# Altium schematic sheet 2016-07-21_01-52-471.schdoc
size 331 x 127 mm; SheetNumber: 1; SheetTotal: 1
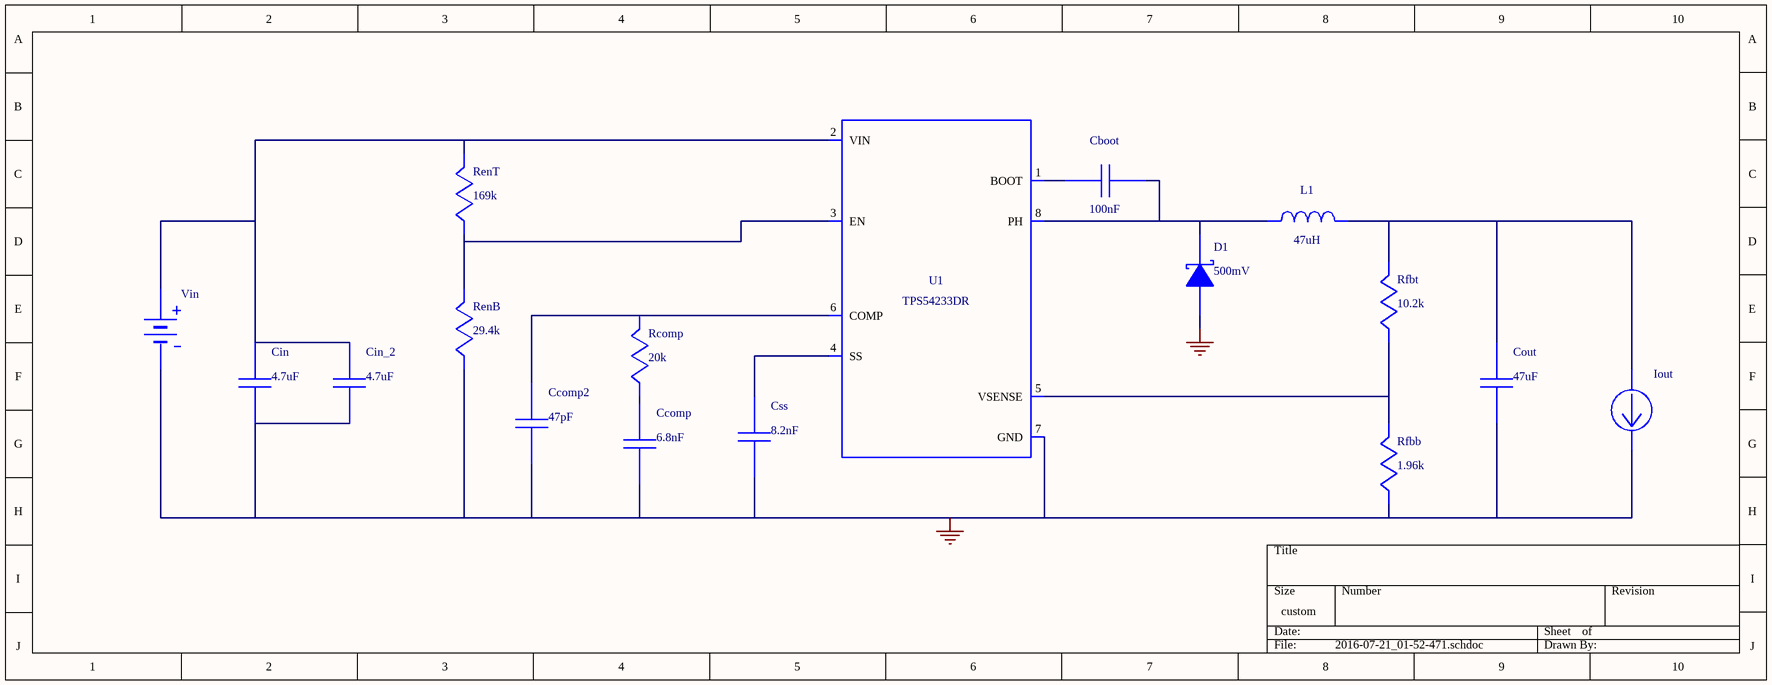
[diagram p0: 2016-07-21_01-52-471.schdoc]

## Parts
Cboot  value 100nF  (hidden comment: GRM155R61A104KA01D)
Ccomp  value 6.8nF  (hidden comment: GRM033R61A682KA01D)
Ccomp2  value 47pF  (hidden comment: CL02C470JO2ANNC)
Cin  value 4.7uF  (hidden comment: GRM32ER71H475KA88L)
Cin_2  value 4.7uF  (hidden comment: GRM32ER71H475KA88L)
Cout  value 47uF  (hidden comment: GRM31CR61A476KE15L)
Css  value 8.2nF  (hidden comment: GRM033R61A822KA01D)
D1  value 500mV  (hidden comment: B240A-13-F)
Iout  WB_CURRENT_LOAD  (value not drawn)
L1  value 47uH  (hidden comment: SRU1048-470Y)
Rcomp  value 20k  (hidden comment: CRCW040220K0FKED)
RenB  value 29.4k  (hidden comment: CRCW040229K4FKED)
RenT  value 169k  (hidden comment: CRCW0402169KFKED)
Rfbb  value 1.96k  (hidden comment: CRCW04021K96FKED)
Rfbt  value 10.2k  (hidden comment: CRCW040210K2FKED)
U1  TPS54231DR  (value not drawn)
Vin  WB_BATTERY  (value not drawn)

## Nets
0: Ccomp.2 Ccomp2.2 Cin.2 Cin_2.2 Cout.2 Css.2 D1.2(A) Iout.2(-) RenB.2 Rfbb.2 U1.7(GND) Vin.2(-)
NetCboot_1: Cboot.1 U1.1(BOOT)
NetCboot_2: Cboot.2 D1.1(K) L1.2 U1.8(PH)
NetCcomp2_1: Ccomp2.1 Rcomp.1 U1.6(COMP)
NetCcomp_1: Ccomp.1 Rcomp.2
NetCin_1: Cin.1 Cin_2.1 RenT.1 U1.2(VIN) Vin.1(+)
NetCout_1: Cout.1 Iout.1(+) L1.1 Rfbt.1
NetCss_1: Css.1 U1.4(SS)
NetRenB_1: RenB.1 RenT.2 U1.3(EN)
NetRfbb_1: Rfbb.1 Rfbt.2 U1.5(VSENSE)

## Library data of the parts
Cboot = GRM155R61A104KA01D: GRM155R61A104KA0; Manufacturer Name: MuRata
Ccomp = GRM033R61A682KA01D: GRM033R61A682KA0; Manufacturer Name: MuRata
Ccomp2 = CL02C470JO2ANNC: Manufacturer Name: Samsung Electro-Mechanics
Cin Cin_2 = GRM32ER71H475KA88L: GRM32ER71H475KA8; Manufacturer Name: MuRata
Cout = GRM31CR61A476KE15L: GRM31CR61A476KE1; Manufacturer Name: MuRata
Css = GRM033R61A822KA01D: GRM033R61A822KA0; Manufacturer Name: MuRata
D1 = B240A-13-F: Manufacturer Name: Diodes Inc.
L1 = SRU1048-470Y: Manufacturer Name: Bourns
Rcomp = CRCW040220K0FKED: Manufacturer Name: Vishay-Dale
RenB = CRCW040229K4FKED: Manufacturer Name: Vishay-Dale
RenT = CRCW0402169KFKED: Manufacturer Name: Vishay-Dale
Rfbb = CRCW04021K96FKED: Manufacturer Name: Vishay-Dale
Rfbt = CRCW040210K2FKED: Manufacturer Name: Vishay-Dale
U1 = TPS54231DR: TPS54233DR; Manufacturer Name: Texas Instruments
